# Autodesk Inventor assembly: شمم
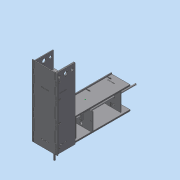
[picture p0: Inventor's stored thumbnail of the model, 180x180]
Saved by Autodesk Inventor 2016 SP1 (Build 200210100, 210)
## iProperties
Created: 2016-06
Part Number: شمم
Document SubType Name: Assembly
Designer: Mohamed A.
Author: Mohamed A.
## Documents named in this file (6)
- C:\Users\Mohamed\Documents\inventor\machine_design\all.iam
- C:\Users\Mohamed\Documents\inventor\machine_design\y-stage\y-stage.iam
- C:\Users\Mohamed\Documents\inventor\machine_design\x-stage\x-stage.iam
- C:\Users\Mohamed\Documents\inventor\machine_design\stepper\nut.ipt
- C:\Users\Mohamed\Documents\inventor\machine_design\x-stage\back.ipt
- C:\Users\Mohamed\Documents\inventor\machine_design\x-stage\side_outer.ipt
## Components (5 placed, 5 different names)
1. y-stage:1 [sub-assembly] — Mate:1, Mate:2, Mate:3, Angle:1
2. x-stage:1 [sub-assembly] — Cylindrical:1, Angle:1, Flush:1, Mate:4, Mate:5, Flush:2, Flush:3, Mate:6
3. nut:1 — Mate:1, Mate:2, Mate:3, Cylindrical:1
4. back:1 — Flush:1, Mate:4, Mate:5
5. side_outer:1 — Flush:2, Flush:3, Mate:6
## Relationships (11: Mate 6, Flush 3, CylindricalJoint 1, Angle 1)
- Mate:1: y-stage:1 ↔ nut:1
- Mate:2: y-stage:1 ↔ nut:1
- Mate:3: y-stage:1 ↔ nut:1
- Cylindrical:1: x-stage:1 ↔ nut:1
- Angle:1: y-stage:1 ↔ x-stage:1
- Flush:1: x-stage:1 ↔ back:1
- Mate:4: x-stage:1 ↔ back:1
- Mate:5: x-stage:1 ↔ back:1
- Flush:2: x-stage:1 ↔ side_outer:1
- Flush:3: x-stage:1 ↔ side_outer:1
- Mate:6: x-stage:1 ↔ side_outer:1
